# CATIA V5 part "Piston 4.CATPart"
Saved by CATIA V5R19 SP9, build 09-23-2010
Part number: Piston 4
Bounding box of the stored display mesh (mm): x -61.798 to 0, y -74.017 to -5.879, z -33.341 to 97.157
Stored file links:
  Y:\projet be 2011-12\Etude cinématique\Piston 4.CATPart
  Y:\projet be 2011-12\piece44.CATPart
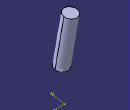
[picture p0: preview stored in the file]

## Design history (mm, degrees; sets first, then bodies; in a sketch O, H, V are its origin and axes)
Body1 (main body)
  DatumSurface1
  DatumCurve1
  Sketch1 on face of DatumSurface1, origin (0, 9.7495, 55.2921), H (-1, 0, 0), V (0, -0.9848, 0.1736)
    circle A1 centre (47.7977, 56.9524) radius 14
    reference projected circle E1 centre (47.7977, 56.9524) radius 14 from edge of DatumCurve1
    reference projected circle E2 centre (47.7977, 56.9524) radius 14 from edge of DatumCurve1
    concentricity: A1 E1
    coincidence: A1 E2
  Pad1: profile Sketch1, direction (0, 0.1736, 0.9848), length 30, opposite side length 80
  Sketch2 on start face of Pad1, origin (0, -4.1424, -23.4926), H (1, 0, 0), V (0, -0.9848, 0.1736)
    circle A1 centre (-47.7977, 56.9524) radius 2.5589
    reference projected circle E1 centre (-47.7977, 56.9524) radius 14 from edge [start face of Pad1 | face of Pad1 from Sketch1.A1]
    concentricity: A1 E1
  Pad2: profile Sketch2, direction (0, -0.1736, -0.9848), length 10
  Plane1: stored without definition
  Sketch3 "point de contact" on end face of Pad2, origin (0, -5.8789, -33.3406), H (1, 0, 0), V (0, -0.9848, 0.1736)
    point P1 (-47.7977, 56.9524)
    reference projected circle E1 centre (-47.7977, 56.9524) radius 2.5589 from edge [face of Pad2 from Sketch2.A1 | end face of Pad2]
    concentricity: P1 E1
  Sketch4, origin (0, 82.0117, -50.1159), H (-1, 0, 0), V (0, -0.9833, 0.1821), geometry linked from another document
  Sketch5 on Plane1, origin (-47.7977, 0, 0), H (0, 1, 0), V (0, 0, 1)
    circle A1 centre (-58.0712, -2.4205) radius 21.3881
    reference projected line E1 (-72.0558, -21.5823) -> (-48.8913, -25.8724) from Sketch4
    reference projected point E2 (-61.966, -23.451) from Sketch3
    tangency: A1 E1
    coincidence: A1 E2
